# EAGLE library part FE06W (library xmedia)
FEMALE HEADER
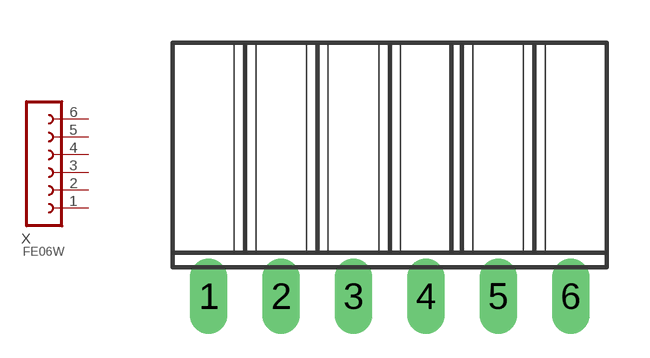
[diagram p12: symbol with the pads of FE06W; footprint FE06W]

Designator prefix X

## FE06W  [FE06W]
1  1  pas
2  2  pas
3  3  pas
4  4  pas
5  5  pas
6  6  pas

## Footprint FE06W (pad centres in mm)
FEMALE HEADER
drill 0.813 long: 1 -6.35,0; 2 -3.81,0; 3 -1.27,0; 4 1.27,0; 5 3.81,0; 6 6.35,0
